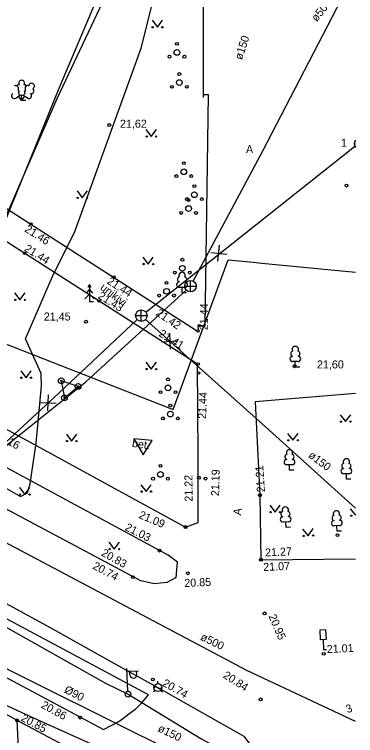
# Model space of a CAD drawing. Extents: x 714038 to 714279, y 6589845 to 6590041.
# Drawn here: x 714249.2 to 714279, y 6589892.8 to 6589955.8 of the extents above; entities that cross this region are included whole.
import ezdxf

# ---------------------------------------------------------------- set-up
doc = ezdxf.new("R2010")
doc.units = 0
for name, color, linetype in [('HALJASTUS', 7, 'Continuous'), ('HOONE', 7, 'Continuous'), ('HOONEDET', 7, 'Continuous'), ('KKAEV', 7, 'Continuous'), ('KORGUS', 7, 'Continuous'), ('KPKAABEL', 7, 'Continuous'), ('LIIKLUS', 7, 'Continuous'), ('MPKAABEL', 7, 'Continuous'), ('POST', 7, 'Continuous'), ('PUU', 7, 'Continuous'), ('SITRASS', 7, 'Continuous'), ('SKTRASS', 7, 'Continuous'), ('TEE', 7, 'Continuous'), ('TORU NR', 7, 'Continuous'), ('TTRASS', 7, 'Continuous'), ('VTRASS', 7, 'Continuous')]:
    doc.layers.add(name, color=color, linetype=linetype)

msp = doc.modelspace()

# ---------------------------------------------------------------- linework, layer by layer
at = {"layer": 'HALJASTUS'}
for p, q in [((714261.178, 6589955.328), (714261.641, 6589954.722)), ((714261.641, 6589954.722), (714262.087, 6589955.328)), ((714260.647, 6589945.77), (714261.11, 6589945.163)), ((714261.11, 6589945.163), (714261.556, 6589945.77)), ((714254.625, 6589940.415), (714255.088, 6589939.808)), ((714255.088, 6589939.808), (714255.534, 6589940.415)), ((714260.381, 6589934.618), (714260.844, 6589934.011)), ((714260.844, 6589934.011), (714261.29, 6589934.618)), ((714249.176, 6589931.491), (714249.64, 6589930.884)), ((714249.64, 6589930.884), (714250.085, 6589931.491)), ((714260.646, 6589925.438), (714261.11, 6589924.831)), ((714261.11, 6589924.831), (714261.555, 6589925.438)), ((714249.708, 6589924.676), (714250.171, 6589924.069)), ((714250.171, 6589924.069), (714250.617, 6589924.676)), ((714277.617, 6589920.837), (714278.08, 6589920.23)), ((714278.08, 6589920.23), (714278.526, 6589920.837)), ((714253.693, 6589919.144), (714254.156, 6589918.538)), ((714254.156, 6589918.538), (714254.602, 6589919.144)), ((714273.017, 6589919.207), (714273.48, 6589918.6)), ((714273.48, 6589918.6), (714273.926, 6589919.207)), ((714260.201, 6589914.719), (714260.665, 6589914.112)), ((714260.665, 6589914.112), (714261.11, 6589914.719)), ((714249.599, 6589914.466), (714250.063, 6589913.859)), ((714250.063, 6589913.859), (714250.508, 6589914.466)), ((714271.467, 6589912.927), (714271.93, 6589912.32)), ((714271.93, 6589912.32), (714272.376, 6589912.927)), ((714278.49, 6589912.615), (714278.95, 6589912.066)), ((714274.33, 6589910.835), (714274.82, 6589910.25)), ((714274.82, 6589910.25), (714275.238, 6589910.876)), ((714257.418, 6589909.687), (714257.882, 6589909.08)), ((714257.882, 6589909.08), (714258.327, 6589909.687))]:
    msp.add_line(p, q, dxfattribs=at)
for centre, radius in [((714261.24, 6589954.722), 0.055), ((714262.069, 6589954.722), 0.055), ((714263.353, 6589953.273), 0.125), ((714263.353, 6589952.523), 0.25), ((714262.703, 6589952.148), 0.125), ((714264.003, 6589952.148), 0.125), ((714263.56, 6589950.63), 0.125), ((714263.56, 6589949.88), 0.25), ((714262.91, 6589949.505), 0.125), ((714264.21, 6589949.505), 0.125), ((714260.709, 6589945.163), 0.055), ((714261.538, 6589945.163), 0.055), ((714263.95, 6589942.831), 0.125), ((714263.95, 6589942.081), 0.25), ((714263.3, 6589941.706), 0.125), ((714264.6, 6589941.706), 0.125), ((714264.872, 6589940.822), 0.125), ((714254.687, 6589939.808), 0.055), ((714255.516, 6589939.808), 0.055), ((714264.222, 6589939.697), 0.125), ((714264.872, 6589940.072), 0.25), ((714265.522, 6589939.697), 0.125), ((714264.366, 6589938.86), 0.25), ((714264.366, 6589939.61), 0.125), ((714263.716, 6589938.485), 0.125), ((714265.016, 6589938.485), 0.125), ((714260.443, 6589934.011), 0.055), ((714261.272, 6589934.011), 0.055), ((714263.823, 6589934.391), 0.125), ((714263.823, 6589933.641), 0.25), ((714263.173, 6589933.266), 0.125), ((714264.473, 6589933.266), 0.125), ((714262.446, 6589932.376), 0.125), ((714262.446, 6589931.626), 0.25), ((714249.239, 6589930.884), 0.055), ((714250.068, 6589930.884), 0.055), ((714261.796, 6589931.251), 0.125), ((714263.096, 6589931.251), 0.125), ((714260.708, 6589924.831), 0.055), ((714261.537, 6589924.831), 0.055), ((714249.77, 6589924.069), 0.055), ((714250.599, 6589924.069), 0.055), ((714262.572, 6589923.929), 0.125), ((714262.572, 6589923.179), 0.25), ((714261.922, 6589922.804), 0.125), ((714263.222, 6589922.804), 0.125), ((714262.777, 6589921.643), 0.125), ((714262.777, 6589920.893), 0.25), ((714262.127, 6589920.518), 0.125), ((714263.427, 6589920.518), 0.125), ((714277.679, 6589920.23), 0.055), ((714278.508, 6589920.23), 0.055), ((714253.755, 6589918.538), 0.055), ((714254.584, 6589918.538), 0.055), ((714273.079, 6589918.6), 0.055), ((714273.908, 6589918.6), 0.055), ((714261.912, 6589916.37), 0.125), ((714261.912, 6589915.62), 0.25), ((714261.262, 6589915.245), 0.125), ((714262.562, 6589915.245), 0.125), ((714249.662, 6589913.859), 0.055), ((714250.49, 6589913.859), 0.055), ((714260.264, 6589914.112), 0.055), ((714261.092, 6589914.112), 0.055), ((714271.529, 6589912.32), 0.055), ((714272.358, 6589912.32), 0.055), ((714278.579, 6589912.012), 0.055), ((714274.419, 6589910.232), 0.055), ((714275.247, 6589910.269), 0.055), ((714257.481, 6589909.08), 0.055), ((714258.31, 6589909.08), 0.055)]:
    msp.add_circle(centre, radius, dxfattribs=at)
at = {"layer": 'HOONE'}
for p, q in [((714261.69, 6589897.33), (714261.69, 6589897.527)), ((714261.34, 6589896.978), (714261.551, 6589897.084)), ((714261.551, 6589897.084), (714261.829, 6589896.876)), ((714261.829, 6589896.876), (714262.04, 6589896.982)), ((714261.443, 6589896.733), (714261.303, 6589896.593)), ((714261.937, 6589896.733), (714262.077, 6589896.593))]:
    msp.add_line(p, q, dxfattribs=at)
for points in [[(714037.81, 6590017.576), (714059.08, 6590006.51), (714072.38, 6589999.69), (714082.14, 6589994.37), (714104.85, 6589981.96), (714150.21, 6589957.43), (714183.55, 6589939.45), (714202.68, 6589928.99), (714214.04, 6589922.75), (714222.92, 6589918.06), (714237.47, 6589910.29), (714252.27, 6589902.23), (714256.602, 6589899.815), (714258.577, 6589898.715), (714261.69, 6589896.98)], [(714261.69, 6589896.98), (714269.19, 6589892.73), (714270.31, 6589891.25), (714277.37, 6589880.57), (714278.95, 6589878.149)]]:
    msp.add_lwpolyline(points, dxfattribs=at)
msp.add_circle((714261.69, 6589896.98), 0.35, dxfattribs=at)
at = {"layer": 'KKAEV'}
for p, q in [((714278.83, 6589944.52), (714278.95, 6589944.52)), ((714264.54, 6589931.58), (714264.54, 6589932.58)), ((714264.04, 6589932.08), (714265.04, 6589932.08)), ((714260.24, 6589929), (714260.24, 6589930)), ((714259.74, 6589929.5), (714260.74, 6589929.5))]:
    msp.add_line(p, q, dxfattribs=at)
for centre in [(714264.54, 6589932.08), (714260.24, 6589929.5)]:
    msp.add_circle(centre, 0.5, dxfattribs=at)
msp.add_arc((714279.33, 6589944.52), 0.5, 139.4488, 220.5512, dxfattribs=at)
at = {"layer": 'KORGUS'}
for centre, radius in [((714257.44, 6589946.17), 0.125), ((714278.16, 6589940.87), 0.125), ((714250.617, 6589937.504), 0.1), ((714250.05, 6589934.946), 0.1), ((714257.844, 6589932.88), 0.1), ((714256.534, 6589930.782), 0.1), ((714255.41, 6589928.97), 0.125), ((714265.307, 6589928.638), 0.1), ((714265.203, 6589928.162), 0.1), ((714265.219, 6589925.268), 0.1), ((714273.63, 6589925.07), 0.125), ((714265.24, 6589924.495), 0.1), ((714265.27, 6589915.33), 0.125), ((714265.84, 6589915.25), 0.125), ((714270.6, 6589913.8), 0.125), ((714264.11, 6589911.01), 0.125), ((714277.37, 6589910.3), 0.125), ((714261.83, 6589908.95), 0.125), ((714270.69, 6589908.15), 0.125), ((714264.3, 6589906.97), 0.125), ((714259.5, 6589906.63), 0.125), ((714271.01, 6589903.46), 0.125), ((714276.17, 6589899.93), 0.125), ((714261.25, 6589897.68), 0.125), ((714270.66, 6589895.94), 0.125), ((714254.9, 6589894.35), 0.125), ((714249.4, 6589894.11), 0.125)]:
    msp.add_circle(centre, radius, dxfattribs=at)
at = {"layer": 'KPKAABEL'}
msp.add_lwpolyline([(714278.95, 6590013.083), (714274.696, 6590002.154), (714268.806, 6589986.746), (714264.689, 6589977.209), (714260.118, 6589965.851), (714258.032, 6589961.24), (714253.05, 6589949.372), (714248.466, 6589938.096), (714247.531, 6589934.989), (714246.389, 6589934.367), (714239.483, 6589937.254), (714226.492, 6589940.819), (714222.669, 6589940.979), (714220.982, 6589941.049), (714220.257, 6589940.365), (714218.76, 6589936.611), (714215.836, 6589929.757), (714212.225, 6589922.206), (714208.098, 6589916.26), (714202.344, 6589907.69)], dxfattribs=at)
at = {"layer": 'LIIKLUS'}
for p, q in [((714253.247, 6589923.811), (714253.529, 6589922.304)), ((714254.72, 6589923.315), (714253.247, 6589923.811)), ((714253.529, 6589922.304), (714254.72, 6589923.315))]:
    msp.add_line(p, q, dxfattribs=at)
for points in [[(714276.332, 6589902.029), (714275.832, 6589902.007)], [(714275.832, 6589902.007), (714275.87, 6589901.158)], [(714276.332, 6589902.029), (714276.37, 6589901.18)], [(714276.37, 6589901.18), (714275.87, 6589901.158)], [(714276.12, 6589901.169), (714276.16, 6589900.27)], [(714276.41, 6589900.281), (714276.16, 6589900.27)]]:
    msp.add_lwpolyline(points, dxfattribs=at)
for centre, radius in [((714253.247, 6589923.811), 0.25), ((714253.247, 6589923.811), 0.05), ((714254.72, 6589923.315), 0.25), ((714254.72, 6589923.315), 0.05), ((714253.529, 6589922.304), 0.25), ((714253.529, 6589922.304), 0.05)]:
    msp.add_circle(centre, radius, dxfattribs=at)
at = {"layer": 'MPKAABEL'}
for p, q in [((714266.928, 6589934.263), (714267.077, 6589935.655)), ((714266.307, 6589935.034), (714267.699, 6589934.885)), ((714262.699, 6589927.958), (714262.774, 6589926.56)), ((714262.037, 6589927.222), (714263.435, 6589927.297)), ((714252.084, 6589921.18), (714252.142, 6589922.578)), ((714251.414, 6589921.908), (714252.813, 6589921.85))]:
    msp.add_line(p, q, dxfattribs=at)
for points in [[(714215.066, 6589943.967), (714214.846, 6589942.32), (714213.494, 6589938.395), (714212.085, 6589935.688), (714211.383, 6589934.84), (714211.278, 6589934.105), (714212.162, 6589933.623), (714233.552, 6589922.923), (714249.701, 6589913.675), (714250.295, 6589914.005), (714250.521, 6589914.785), (714251.05, 6589918.335), (714251.513, 6589923.366), (714251.481, 6589924.441), (714250.114, 6589927.476), (714252.56, 6589933.122), (714254.403, 6589936.762), (714260.237, 6589952.896), (714261.787, 6589959.195)], [(714231.9, 6589911.052), (714237.45, 6589907.982), (714245.1, 6589904.132), (714257.12, 6589897.374), (714259.08, 6589896.4)], [(714259.08, 6589896.4), (714265.45, 6589892.52), (714272.58, 6589888.54), (714277.82, 6589885.3), (714278.95, 6589884.501)]]:
    msp.add_lwpolyline(points, dxfattribs=at)
at = {"layer": 'POST'}
for p, q in [((714259.069, 6589896.65), (714258.979, 6589898.648)), ((714258.991, 6589898.398), (714259.99, 6589898.443)), ((714259.231, 6589898.088), (714259.217, 6589898.408)), ((714259.844, 6589898.115), (714259.829, 6589898.436))]:
    msp.add_line(p, q, dxfattribs=at)
msp.add_circle((714259.08, 6589896.4), 0.25, dxfattribs=at)
msp.add_arc((714259.537, 6589898.101), 0.306, 182.5627, 2.5627, dxfattribs=at)
at = {"layer": 'PUU'}
for p, q in [((714249.28, 6589948.531), (714249.64, 6589948.786)), ((714249.79, 6589948.311), (714249.515, 6589948.696)), ((714249.64, 6589948.786), (714249.935, 6589948.786)), ((714249.79, 6589948.311), (714249.79, 6589948.786)), ((714249.79, 6589948.311), (714250.06, 6589948.701)), ((714249.935, 6589948.786), (714250.295, 6589948.541)), ((714250.17, 6589948.311), (714249.79, 6589948.311)), ((714255.715, 6589932.215), (714255.565, 6589931.965)), ((714255.865, 6589931.965), (714255.715, 6589932.215)), ((714255.715, 6589932.215), (714255.715, 6589930.715)), ((714255.715, 6589931.815), (714255.415, 6589931.465)), ((714256.015, 6589931.465), (714255.715, 6589931.815)), ((714264.039, 6589931.974), (714263.559, 6589931.974)), ((714263.799, 6589931.499), (714263.799, 6589931.974)), ((714255.715, 6589931.365), (714255.315, 6589930.965)), ((714256.115, 6589930.965), (714255.715, 6589931.365)), ((714264.179, 6589931.499), (714263.799, 6589931.499)), ((714256.075, 6589930.715), (714255.715, 6589930.715)), ((714273.93, 6589925.485), (714273.45, 6589925.485)), ((714273.69, 6589925.01), (714273.69, 6589925.485)), ((714274.07, 6589925.01), (714273.69, 6589925.01)), ((714273.42, 6589916.455), (714272.94, 6589916.455)), ((714273.18, 6589915.98), (714273.18, 6589916.455)), ((714273.56, 6589915.98), (714273.18, 6589915.98)), ((714278.39, 6589915.665), (714277.91, 6589915.665)), ((714278.15, 6589915.19), (714278.15, 6589915.665)), ((714278.53, 6589915.19), (714278.15, 6589915.19)), ((714273.099, 6589911.465), (714272.619, 6589911.444)), ((714272.88, 6589910.98), (714272.859, 6589911.455)), ((714273.26, 6589910.997), (714272.88, 6589910.98)), ((714277.569, 6589911.135), (714277.089, 6589911.114)), ((714277.35, 6589910.65), (714277.329, 6589911.125)), ((714277.73, 6589910.667), (714277.35, 6589910.65))]:
    msp.add_line(p, q, dxfattribs=at)
for points in [[(714249.377, 6589949.598), (714249.48, 6589949.496), (714249.495, 6589949.466), (714249.495, 6589949.411), (714249.48, 6589949.321), (714249.48, 6589949.276), (714249.5, 6589949.196), (714249.54, 6589949.106), (714249.55, 6589949.061), (714249.545, 6589949.016), (714249.53, 6589948.951), (714249.53, 6589948.921), (714249.55, 6589948.881), (714249.575, 6589948.851), (714249.64, 6589948.786)], [(714250.194, 6589949.612), (714250.1, 6589949.496), (714250.085, 6589949.466), (714250.085, 6589949.411), (714250.1, 6589949.321), (714250.105, 6589949.276), (714250.085, 6589949.196), (714250.045, 6589949.106), (714250.035, 6589949.061), (714250.04, 6589949.016), (714250.055, 6589948.951), (714250.055, 6589948.921), (714250.035, 6589948.881), (714250.01, 6589948.851), (714249.94, 6589948.786)]]:
    msp.add_lwpolyline(points, dxfattribs=at)
for centre, radius, start, end in [((714249.79, 6589949.831), 0.256, 90.00126, 211.01588), ((714249.79, 6589949.831), 0.256, 328.98412, 89.99874), ((714249.293, 6589949.415), 0.202, 65.23821, 130.74121), ((714249.552, 6589949.498), 0.202, 84.79647, 150.29947), ((714250.027, 6589949.498), 0.202, 34.38566, 95.20353), ((714250.266, 6589949.424), 0.202, 50.31726, 111.13512), ((714250.65, 6589949.564), 0.256, 55.52204, 176.53666), ((714250.63, 6589949.146), 0.224, 252.52354, 55.59181), ((714250.65, 6589949.564), 0.256, 294.50491, 55.51952), ((714249.144, 6589948.725), 0.237, 125.53768, 305.53661), ((714250.428, 6589948.737), 0.237, 235.52186, 55.52078), ((714263.629, 6589932.672), 0.233, 109.02174, 253.14154), ((714263.799, 6589933.019), 0.277, 332.5799, 207.4201), ((714263.969, 6589932.672), 0.233, 286.85082, 70.98591), ((714263.561, 6589932.211), 0.238, 90.0016, 269.3953), ((714264.036, 6589932.211), 0.238, 270.6047, 89.9984), ((714273.69, 6589926.53), 0.277, 332.5799, 207.4201), ((714273.453, 6589925.722), 0.238, 90.0016, 269.3953), ((714273.52, 6589926.183), 0.233, 109.02174, 253.14154), ((714273.86, 6589926.183), 0.233, 286.85082, 70.98591), ((714273.927, 6589925.722), 0.238, 270.6047, 89.9984), ((714273.18, 6589917.5), 0.277, 332.5799, 207.4201), ((714273.01, 6589917.153), 0.233, 109.02174, 253.14154), ((714273.35, 6589917.153), 0.233, 286.85082, 70.98591), ((714272.943, 6589916.692), 0.238, 90.0016, 269.3953), ((714273.417, 6589916.692), 0.238, 270.6047, 89.9984), ((714277.98, 6589916.363), 0.233, 109.02174, 253.14154), ((714278.15, 6589916.71), 0.277, 332.5799, 207.4201), ((714278.32, 6589916.363), 0.233, 286.85082, 70.98591), ((714277.913, 6589915.902), 0.238, 90.0016, 269.3953), ((714278.387, 6589915.902), 0.238, 270.6047, 89.9984), ((714272.812, 6589912.498), 0.277, 335.1426, 209.9828), ((714272.658, 6589912.144), 0.233, 111.58444, 255.70424), ((714272.997, 6589912.159), 0.233, 289.41352, 73.54861), ((714277.128, 6589911.814), 0.233, 111.58444, 255.70424), ((714277.282, 6589912.168), 0.277, 335.1426, 209.9828), ((714277.467, 6589911.829), 0.233, 289.41352, 73.54861), ((714272.611, 6589911.681), 0.238, 92.5643, 271.958), ((714273.085, 6589911.702), 0.238, 273.16741, 92.5611), ((714277.081, 6589911.351), 0.238, 92.5643, 271.958), ((714277.555, 6589911.372), 0.238, 273.16741, 92.5611)]:
    msp.add_arc(centre, radius, start, end, dxfattribs=at)
at = {"layer": 'SITRASS'}
msp.add_lwpolyline([(714228.11, 6589904.769), (714235.097, 6589901.472), (714246.809, 6589896.155), (714249.743, 6589894.816), (714250.57, 6589894.44), (714264.7, 6589888.06), (714272.32, 6589884.65)], dxfattribs=at)
at = {"layer": 'SKTRASS'}
for points in [[(714264.775, 6589932.521), (714270.85, 6589943.92), (714278.95, 6589959.571)], [(714260.629, 6589929.814), (714278.863, 6589944.287)], [(714242.415, 6589913.339), (714255.39, 6589923.72), (714264.171, 6589931.743)], [(714247.18, 6589917.34), (714253.06, 6589922.75), (714259.876, 6589929.158)], [(714278.95, 6589912.658), (714271.08, 6589919.77), (714260.612, 6589929.166)], [(714278.95, 6589894.02), (714269.47, 6589898.47), (714242.461, 6589912.782)]]:
    msp.add_lwpolyline(points, dxfattribs=at)
at = {"layer": 'TEE'}
for points in [[(714265.679, 6589948.579), (714265.679, 6589961.34)], [(714237.479, 6589956.311), (714237.505, 6589955.772), (714237.56, 6589955.119), (714237.618, 6589954.629), (714237.686, 6589954.16), (714237.775, 6589953.648), (714237.953, 6589952.822), (714238.519, 6589952.862), (714241.392, 6589953.057), (714241.599, 6589949.716), (714246.102, 6589949.982), (714246.498, 6589940.136), (714265.073, 6589928.211), (714265.223, 6589928.249)], [(714265.216, 6589928.602), (714265.814, 6589928.61), (714266.104, 6589948.802), (714265.679, 6589948.799)], [(714263.275, 6589906.612), (714262.481, 6589906.156), (714261.368, 6589906.05), (714260.213, 6589906.315), (714240.788, 6589916.652), (714217.995, 6589928.881), (714199.241, 6589938.974), (714197.452, 6589940.713), (714195.768, 6589942.431), (714184.455, 6589948.554)], [(714263.275, 6589906.612), (714263.414, 6589907.94), (714262.577, 6589908.551), (714241.037, 6589920.211), (714219.611, 6589931.838), (714198.955, 6589942.945), (714197.611, 6589943.352), (714197.847, 6589943.789), (714196.868, 6589944.026)], [(714217.759, 6589936.392), (714238.65, 6589925.109), (714247.372, 6589920.348), (714247.69, 6589919.978), (714264.11, 6589911.01), (714265.191, 6589911.398), (714265.199, 6589917.222), (714265.151, 6589925.259), (714246.63, 6589937.111), (714247.349, 6589920.604), (714247.372, 6589920.348)], [(714265.223, 6589928.249), (714265.216, 6589928.602)], [(714278.95, 6589922.701), (714270.19, 6589921.97), (714270.59, 6589913.8), (714270.594, 6589913.795), (714270.685, 6589908.149), (714278.95, 6589908.24)], [(714259.587, 6589918.715), (714260.402, 6589917.326), (714261.183, 6589918.581), (714259.587, 6589918.715)], [(714260.872, 6589896.331), (714241.905, 6589906.497)], [(714241.895, 6589901.346), (714256.945, 6589893.296), (714258.288, 6589894.014), (714258.288, 6589894.014), (714258.288, 6589894.014), (714259.596, 6589894.991), (714259.596, 6589894.991), (714259.723, 6589895.1), (714259.723, 6589895.1), (714260.278, 6589895.636), (714260.278, 6589895.636), (714260.278, 6589895.636), (714260.872, 6589896.331)], [(714263.472, 6589878.412), (714265.767, 6589878.509), (714265.522, 6589885.849), (714264.63, 6589886.315), (714264.168, 6589886.556), (714263.52, 6589886.894), (714261.567, 6589887.913), (714261.242, 6589888.082), (714254.879, 6589891.188), (714249.398, 6589894.111), (714248.724, 6589894.462), (714243.421, 6589897.164)], [(714249.729, 6589887.538), (714249.398, 6589894.111)]]:
    msp.add_lwpolyline(points, dxfattribs=at)
at = {"layer": 'TTRASS'}
msp.add_lwpolyline([(714232.746, 6589933.149), (714263.03, 6589921.28), (714267.83, 6589934.38), (714270.013, 6589934.171), (714270.776, 6589934.097), (714278.95, 6589933.313)], dxfattribs=at)
at = {"layer": 'VTRASS'}
for points in [[(714234.193, 6589907.469), (714237.059, 6589913.816), (714240.349, 6589920.042), (714244.05, 6589926.694), (714247.419, 6589935.922), (714252.894, 6589948.5), (714258.093, 6589959.582), (714259.692, 6589963.065), (714262.845, 6589969.359)], [(714233.488, 6589906.247), (714239.337, 6589903.162), (714263.403, 6589891.181), (714275.749, 6589884.323), (714275.315, 6589880.416), (714276.224, 6589845.18)]]:
    msp.add_lwpolyline(points, dxfattribs=at)

# ---------------------------------------------------------------- texts
at = {"layer": 'HOONEDET'}
msp.add_text('bet.', height=0.7, rotation=351.65842, dxfattribs=at).set_placement((714259.394, 6589918.026))
at = {"layer": 'KORGUS'}
for s, p in [('21,62', (714258.376, 6589945.935)), ('21,45', (714251.726, 6589929.075)), ('21,60', (714275.579, 6589924.885))]:
    msp.add_text(s, height=0.7, dxfattribs=at).set_placement(p)
for s, rotation, p in [(' 21.46', 327.49666, (714249.765, 6589937.041)), (' 21.44 ', 328.16066, (714249.744, 6589935.334)), (' 21.44', 327.51431, (714256.963, 6589932.486)), (' 21.43', 327.54066, (714256.18, 6589931.205)), (' 21.44', 88.82124, (714266.027, 6589927.963)), (' 21.42', 325.88298, (714261.238, 6589929.722)), (' 21.41', 328.11322, (714261.482, 6589927.889)), (' 21.44', 87.21541, (714265.871, 6589920.201)), ('21.16', 331.84581, (714247.33, 6589918.88)), ('21.19', 88.58076, (714267.03, 6589913.71)), ('21.21', 93.6523, (714271.04, 6589914.08)), ('21.22', 90.74082, (714264.73, 6589913.24)), ('21.09', 336.83679, (714259.96, 6589911.83)), ('21.03', 333.07011, (714258.75, 6589910.78)), ('20.83', 330.53998, (714256.68, 6589908.56)), ('21.27', 2.55816, (714271.06, 6589908.44)), ('20.74', 331.58168, (714255.93, 6589907.41)), ('21.07', 2.55816, (714270.9, 6589907.17)), ('20.85', 2.55816, (714264.01, 6589905.77)), ('20.95', 293.32162, (714271.33, 6589903.22)), ('21.01', 2.55816, (714276.45, 6589899.99)), ('20.84', 327.55264, (714267.32, 6589897.88)), ('20.74', 330.23769, (714262.02, 6589897.17)), ('20.86', 331.04103, (714251.43, 6589895.25)), ('20.85', 331.71798, (714249.67, 6589894.11))]:
    msp.add_text(s, height=0.7, rotation=rotation, dxfattribs=at).set_placement(p)
at = {"layer": 'TEE'}
msp.add_text('A', height=0.7, dxfattribs=at).set_placement((714269.385, 6589943.714))
for s, rotation, p in [('unikivi', 322.45128, (714256.591, 6589931.849)), ('A', 82.94601, (714268.95, 6589912.01))]:
    msp.add_text(s, height=0.7, rotation=rotation, dxfattribs=at).set_placement(p)
at = {"layer": 'TORU NR'}
for s, rotation, p in [('ø500', 51.06037, (714275.555, 6589955.156)), ('ø150', 71.84301, (714269.026, 6589951.819)), ('1', 359.97878, (714277.668, 6589944.265)), ('ø150', 322.98296, (714274.762, 6589917.165)), ('ø500', 333.98862, (714265.335, 6589901.174)), ('3', 20.87258, (714278.253, 6589894.726)), ('ø150', 333.98862, (714261.618, 6589893.183))]:
    msp.add_text(s, height=0.7, rotation=rotation, dxfattribs=at).set_placement(p)
at = {"layer": 'VTRASS'}
msp.add_text('%%c90', height=0.7, rotation=332.53299, dxfattribs=at).set_placement((714253.446, 6589896.57))

doc.saveas('drawing.dxf')
